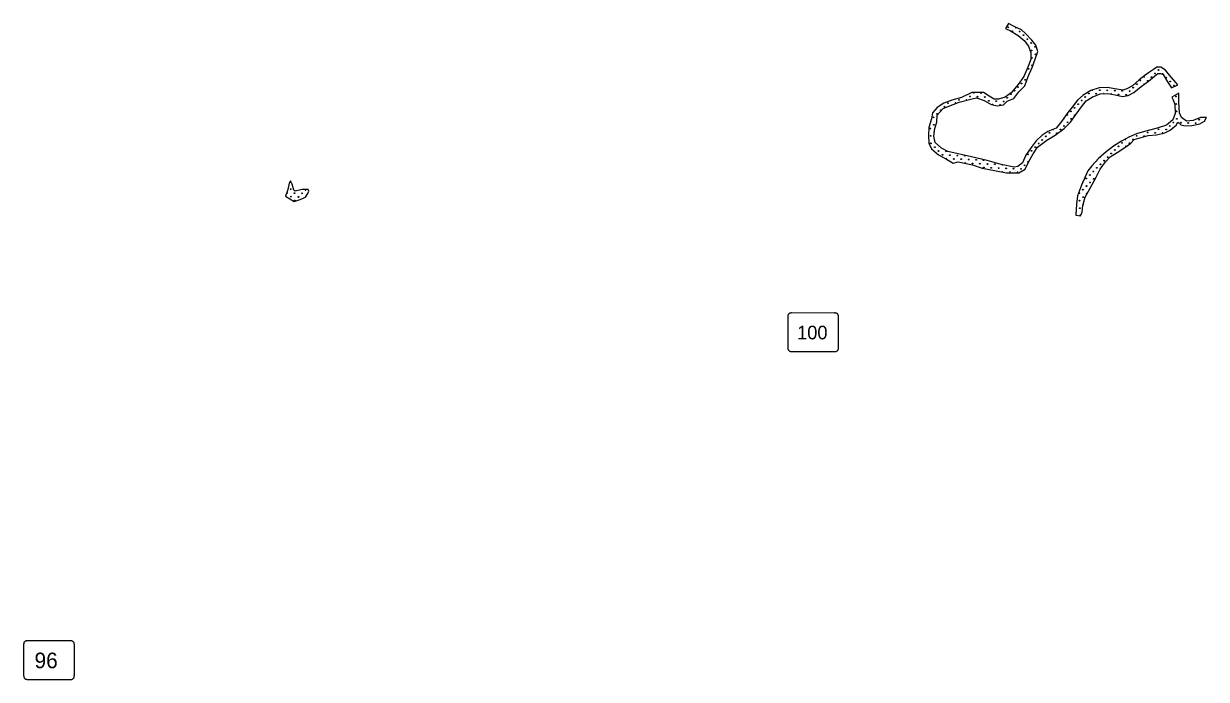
# Model space of a CAD drawing. Extents: x 1612280 to 1883141, y 560852 to 780851.
# Drawn here: x 1662813 to 1694849, y 612064 to 629833 of the extents above; entities that cross this region are included whole.
import ezdxf

# ---------------------------------------------------------------- set-up
doc = ezdxf.new("R2010")
doc.units = 0
for name, color, linetype in [('DESIGN - ROW - Slope Lines', 7, 'Continuous'), ('DESIGN - SCRATCH - User 1', 7, 'Continuous'), ('DESIGN - TRAFFIC CONTROL PERMANENT - Pavement Marking Text', 7, 'Continuous')]:
    doc.layers.add(name, color=color, linetype=linetype)

msp = doc.modelspace()

# ---------------------------------------------------------------- linework, layer by layer
at = {"layer": 'DESIGN - ROW - Slope Lines'}
for p, q in [((1683512, 621892), (1683512, 621060)), ((1683512, 621892), (1683512, 621060)), ((1662813, 613006), (1662813, 612174)), ((1662813, 613006), (1662813, 612174))]:
    msp.add_line(p, q, dxfattribs=at)
for points in [[(1684885, 621881), (1684885, 621889), (1684884, 621897), (1684883, 621912), (1684882, 621922), (1684880, 621933), (1684878, 621939), (1684875, 621945), (1684871, 621953), (1684865, 621960), (1684860, 621966), (1684855, 621971), (1684850, 621975), (1684843, 621980), (1684838, 621983), (1684830, 621987), (1684824, 621989), (1684817, 621990), (1684808, 621992), (1684799, 621992), (1684791, 621993), (1684778, 621993), (1684769, 621992), (1683612, 621993), (1683602, 621993), (1683592, 621992), (1683583, 621991), (1683574, 621990), (1683570, 621988), (1683562, 621985), (1683556, 621982), (1683551, 621979), (1683542, 621972), (1683536, 621966), (1683531, 621960), (1683527, 621955), (1683521, 621945), (1683518, 621938), (1683516, 621933), (1683515, 621929), (1683514, 621925), (1683513, 621918), (1683512, 621909), (1683512, 621901), (1683512, 621894), (1683512, 621876)], [(1684885, 621881), (1684885, 621889), (1684884, 621897), (1684883, 621912), (1684882, 621922), (1684880, 621933), (1684878, 621939), (1684875, 621945), (1684871, 621953), (1684865, 621960), (1684860, 621966), (1684855, 621971), (1684850, 621975), (1684843, 621980), (1684838, 621983), (1684830, 621987), (1684824, 621989), (1684817, 621990), (1684808, 621992), (1684799, 621992), (1684791, 621993), (1684778, 621993), (1684769, 621992), (1683612, 621993), (1683602, 621993), (1683592, 621992), (1683583, 621991), (1683574, 621990), (1683570, 621988), (1683562, 621985), (1683556, 621982), (1683551, 621979), (1683542, 621972), (1683536, 621966), (1683531, 621960), (1683527, 621955), (1683521, 621945), (1683518, 621938), (1683516, 621933), (1683515, 621929), (1683514, 621925), (1683513, 621918), (1683512, 621909), (1683512, 621901), (1683512, 621894), (1683512, 621876)], [(1684775, 620950), (1684795, 620951), (1684812, 620951), (1684823, 620953), (1684835, 620958), (1684846, 620965), (1684855, 620972), (1684863, 620980), (1684869, 620987), (1684875, 620997), (1684879, 621005), (1684882, 621012), (1684883, 621020), (1684884, 621028), (1684884, 621038), (1684885, 621061), (1684885, 621881)], [(1684775, 620950), (1684795, 620951), (1684812, 620951), (1684823, 620953), (1684835, 620958), (1684846, 620965), (1684855, 620972), (1684863, 620980), (1684869, 620987), (1684875, 620997), (1684879, 621005), (1684882, 621012), (1684883, 621020), (1684884, 621028), (1684884, 621038), (1684885, 621061), (1684885, 621881)], [(1683512, 621060), (1683512, 621051), (1683512, 621041), (1683513, 621031), (1683514, 621022), (1683516, 621013), (1683519, 621005), (1683522, 620998), (1683526, 620990), (1683532, 620983), (1683537, 620977), (1683545, 620970), (1683552, 620965), (1683560, 620960), (1683568, 620956), (1683577, 620953), (1683584, 620952), (1683599, 620951), (1683618, 620950), (1684775, 620950)], [(1683512, 621060), (1683512, 621051), (1683512, 621041), (1683513, 621031), (1683514, 621022), (1683516, 621013), (1683519, 621005), (1683522, 620998), (1683526, 620990), (1683532, 620983), (1683537, 620977), (1683545, 620970), (1683552, 620965), (1683560, 620960), (1683568, 620956), (1683577, 620953), (1683584, 620952), (1683599, 620951), (1683618, 620950), (1684775, 620950)], [(1664186, 612995), (1664186, 613003), (1664186, 613011), (1664185, 613026), (1664183, 613036), (1664181, 613047), (1664179, 613053), (1664176, 613059), (1664172, 613067), (1664166, 613074), (1664162, 613080), (1664156, 613085), (1664151, 613089), (1664145, 613094), (1664140, 613096), (1664131, 613100), (1664125, 613103), (1664118, 613104), (1664109, 613105), (1664101, 613106), (1664092, 613107), (1664080, 613107), (1664070, 613106), (1662913, 613107), (1662904, 613107), (1662893, 613106), (1662884, 613105), (1662875, 613103), (1662871, 613102), (1662864, 613099), (1662857, 613096), (1662852, 613092), (1662843, 613086), (1662837, 613080), (1662832, 613074), (1662828, 613069), (1662822, 613059), (1662819, 613052), (1662817, 613047), (1662816, 613043), (1662816, 613039), (1662815, 613032), (1662814, 613023), (1662813, 613015), (1662813, 613008), (1662813, 612990)], [(1664186, 612995), (1664186, 613003), (1664186, 613011), (1664185, 613026), (1664183, 613036), (1664181, 613047), (1664179, 613053), (1664176, 613059), (1664172, 613067), (1664166, 613074), (1664162, 613080), (1664156, 613085), (1664151, 613089), (1664145, 613094), (1664140, 613096), (1664131, 613100), (1664125, 613103), (1664118, 613104), (1664109, 613105), (1664101, 613106), (1664092, 613107), (1664080, 613107), (1664070, 613106), (1662913, 613107), (1662904, 613107), (1662893, 613106), (1662884, 613105), (1662875, 613103), (1662871, 613102), (1662864, 613099), (1662857, 613096), (1662852, 613092), (1662843, 613086), (1662837, 613080), (1662832, 613074), (1662828, 613069), (1662822, 613059), (1662819, 613052), (1662817, 613047), (1662816, 613043), (1662816, 613039), (1662815, 613032), (1662814, 613023), (1662813, 613015), (1662813, 613008), (1662813, 612990)], [(1664076, 612064), (1664097, 612065), (1664114, 612065), (1664124, 612067), (1664136, 612072), (1664147, 612079), (1664156, 612085), (1664164, 612093), (1664171, 612101), (1664177, 612111), (1664180, 612119), (1664183, 612126), (1664184, 612134), (1664185, 612142), (1664185, 612152), (1664186, 612175), (1664186, 612995)], [(1664076, 612064), (1664097, 612065), (1664114, 612065), (1664124, 612067), (1664136, 612072), (1664147, 612079), (1664156, 612085), (1664164, 612093), (1664171, 612101), (1664177, 612111), (1664180, 612119), (1664183, 612126), (1664184, 612134), (1664185, 612142), (1664185, 612152), (1664186, 612175), (1664186, 612995)], [(1662813, 612174), (1662813, 612165), (1662814, 612155), (1662814, 612145), (1662816, 612136), (1662817, 612127), (1662820, 612119), (1662823, 612112), (1662828, 612104), (1662833, 612097), (1662839, 612091), (1662846, 612084), (1662853, 612079), (1662861, 612074), (1662870, 612070), (1662878, 612067), (1662886, 612066), (1662901, 612065), (1662919, 612064), (1664076, 612064)], [(1662813, 612174), (1662813, 612165), (1662814, 612155), (1662814, 612145), (1662816, 612136), (1662817, 612127), (1662820, 612119), (1662823, 612112), (1662828, 612104), (1662833, 612097), (1662839, 612091), (1662846, 612084), (1662853, 612079), (1662861, 612074), (1662870, 612070), (1662878, 612067), (1662886, 612066), (1662901, 612065), (1662919, 612064), (1664076, 612064)]]:
    msp.add_lwpolyline(points, dxfattribs=at)
at = {"layer": 'DESIGN - SCRATCH - User 1'}
for points in [[(1689491, 629833), (1689407, 629705), (1689543, 629635), (1689754, 629510), (1689910, 629378), (1690035, 629226), (1690091, 629045), (1690091, 628865), (1690015, 628656), (1689904, 628403), (1689754, 628184), (1689560, 627955), (1689400, 627844), (1689220, 627785), (1689102, 627785), (1688970, 627872), (1688814, 627965), (1688495, 627969)], [(1689491, 629833), (1689407, 629705), (1689543, 629635), (1689754, 629510), (1689910, 629378), (1690035, 629226), (1690091, 629045), (1690091, 628865), (1690015, 628656), (1689904, 628403), (1689754, 628184), (1689560, 627955), (1689400, 627844), (1689220, 627785), (1689102, 627785), (1688970, 627872), (1688814, 627965), (1688495, 627969)], [(1688505, 627799), (1688620, 627820), (1688832, 627747), (1689022, 627646), (1689189, 627608), (1689355, 627629), (1689453, 627736), (1689636, 627809), (1689768, 627986), (1689931, 628146), (1690025, 628403), (1690133, 628646), (1690212, 628875), (1690282, 629076), (1690230, 629246), (1690126, 629385), (1689949, 629566), (1689845, 629666), (1689661, 629743), (1689491, 629833)], [(1688505, 627799), (1688620, 627820), (1688832, 627747), (1689022, 627646), (1689189, 627608), (1689355, 627629), (1689453, 627736), (1689636, 627809), (1689768, 627986), (1689931, 628146), (1690025, 628403), (1690133, 628646), (1690212, 628875), (1690282, 629076), (1690230, 629246), (1690126, 629385), (1689949, 629566), (1689845, 629666), (1689661, 629743), (1689491, 629833)], [(1694074, 628179), (1693853, 628436), (1693741, 628575), (1693620, 628650), (1693504, 628650), (1693415, 628594), (1693228, 628463), (1693030, 628308), (1692846, 628149), (1692697, 628067), (1692589, 628034), (1692421, 628057), (1692164, 628107), (1691950, 628097), (1691719, 628021), (1691515, 627896), (1691357, 627764), (1691212, 627573), (1691095, 627426)], [(1694074, 628179), (1693853, 628436), (1693741, 628575), (1693620, 628650), (1693504, 628650), (1693415, 628594), (1693228, 628463), (1693030, 628308), (1692846, 628149), (1692697, 628067), (1692589, 628034), (1692421, 628057), (1692164, 628107), (1691950, 628097), (1691719, 628021), (1691515, 627896), (1691357, 627764), (1691212, 627573), (1691095, 627426)], [(1691171, 627162), (1691324, 627381), (1691466, 627579), (1691594, 627737), (1691759, 627843), (1691976, 627929), (1692184, 627942), (1692381, 627906), (1692576, 627856), (1692727, 627886), (1692885, 627971), (1693079, 628130), (1693284, 628275), (1693448, 628410), (1693537, 628479), (1693606, 628479), (1693679, 628453), (1693797, 628258), (1693906, 628090), (1694074, 628179)], [(1691171, 627162), (1691324, 627381), (1691466, 627579), (1691594, 627737), (1691759, 627843), (1691976, 627929), (1692184, 627942), (1692381, 627906), (1692576, 627856), (1692727, 627886), (1692885, 627971), (1693079, 628130), (1693284, 628275), (1693448, 628410), (1693537, 628479), (1693606, 628479), (1693679, 628453), (1693797, 628258), (1693906, 628090), (1694074, 628179)], [(1688495, 627969), (1688221, 627833), (1687951, 627764), (1687740, 627681), (1687559, 627563), (1687434, 627418), (1687404, 627250), (1687332, 627022), (1687325, 626805), (1687335, 626597), (1687404, 626442), (1687592, 626274), (1687810, 626165), (1687987, 626053), (1688123, 626086), (1688514, 626004)], [(1688495, 627969), (1688221, 627833), (1687951, 627764), (1687740, 627681), (1687559, 627563), (1687434, 627418), (1687404, 627250), (1687332, 627022), (1687325, 626805), (1687335, 626597), (1687404, 626442), (1687592, 626274), (1687810, 626165), (1687987, 626053), (1688123, 626086), (1688514, 626004)], [(1694849, 627291), (1694694, 627289), (1694491, 627206), (1694311, 627186), (1694178, 627286), (1694123, 627416), (1694101, 627713), (1694101, 627951), (1693915, 627840)], [(1694849, 627291), (1694694, 627289), (1694491, 627206), (1694311, 627186), (1694178, 627286), (1694123, 627416), (1694101, 627713), (1694101, 627951), (1693915, 627840)], [(1688491, 626228), (1687846, 626366), (1687675, 626459), (1687500, 626614), (1687470, 626782), (1687490, 626996), (1687549, 627167), (1687553, 627352), (1687724, 627530), (1687826, 627583), (1688152, 627704), (1688505, 627799)], [(1688491, 626228), (1687846, 626366), (1687675, 626459), (1687500, 626614), (1687470, 626782), (1687490, 626996), (1687549, 627167), (1687553, 627352), (1687724, 627530), (1687826, 627583), (1688152, 627704), (1688505, 627799)], [(1693915, 627840), (1693948, 627765), (1693996, 627638), (1694001, 627402), (1693940, 627225), (1693766, 627078), (1693519, 626998), (1693170, 626906)], [(1693915, 627840), (1693948, 627765), (1693996, 627638), (1694001, 627402), (1693940, 627225), (1693766, 627078), (1693519, 626998), (1693170, 626906)], [(1691095, 627426), (1690924, 627179), (1690779, 626998), (1690555, 626909), (1690393, 626800), (1690239, 626658), (1690104, 626480), (1689962, 626269), (1689866, 626058), (1689741, 625959), (1689643, 625940), (1689287, 626019), (1688915, 626121), (1688491, 626228)], [(1691095, 627426), (1690924, 627179), (1690779, 626998), (1690555, 626909), (1690393, 626800), (1690239, 626658), (1690104, 626480), (1689962, 626269), (1689866, 626058), (1689741, 625959), (1689643, 625940), (1689287, 626019), (1688915, 626121), (1688491, 626228)], [(1694076, 627161), (1694159, 627092), (1694273, 627067), (1694455, 627072), (1694671, 627117), (1694796, 627194), (1694849, 627291)], [(1694076, 627161), (1694159, 627092), (1694273, 627067), (1694455, 627072), (1694671, 627117), (1694796, 627194), (1694849, 627291)], [(1688514, 626004), (1688780, 625917), (1689106, 625854), (1689432, 625788), (1689771, 625791), (1689942, 625893), (1690044, 626098), (1690156, 626305), (1690278, 626487), (1690529, 626675), (1690756, 626813), (1690993, 626988), (1691171, 627162)], [(1688514, 626004), (1688780, 625917), (1689106, 625854), (1689432, 625788), (1689771, 625791), (1689942, 625893), (1690044, 626098), (1690156, 626305), (1690278, 626487), (1690529, 626675), (1690756, 626813), (1690993, 626988), (1691171, 627162)], [(1691309, 624640), (1691437, 624625), (1691485, 624724), (1691503, 624903), (1691569, 625134), (1691701, 625376), (1691866, 625669), (1691972, 625892), (1692115, 626090), (1692239, 626226), (1692433, 626339), (1692671, 626497), (1692806, 626596), (1692898, 626691), (1693275, 626804), (1693498, 626823), (1693725, 626870), (1693872, 626944), (1694033, 627079), (1694076, 627161)], [(1691309, 624640), (1691437, 624625), (1691485, 624724), (1691503, 624903), (1691569, 625134), (1691701, 625376), (1691866, 625669), (1691972, 625892), (1692115, 626090), (1692239, 626226), (1692433, 626339), (1692671, 626497), (1692806, 626596), (1692898, 626691), (1693275, 626804), (1693498, 626823), (1693725, 626870), (1693872, 626944), (1694033, 627079), (1694076, 627161)], [(1693170, 626906), (1692953, 626848), (1692751, 626757), (1692550, 626647), (1692334, 626511), (1692136, 626361), (1691931, 626182), (1691745, 625984), (1691635, 625848), (1691463, 625456), (1691360, 625171), (1691335, 624940), (1691309, 624640)], [(1693170, 626906), (1692953, 626848), (1692751, 626757), (1692550, 626647), (1692334, 626511), (1692136, 626361), (1691931, 626182), (1691745, 625984), (1691635, 625848), (1691463, 625456), (1691360, 625171), (1691335, 624940), (1691309, 624640)], [(1670041, 625571), (1670009, 625506), (1669973, 625343), (1669908, 625160)], [(1670041, 625571), (1670009, 625506), (1669973, 625343), (1669908, 625160)], [(1670521, 625335), (1670361, 625340), (1670166, 625293), (1670133, 625320), (1670089, 625480), (1670041, 625571)], [(1670521, 625335), (1670361, 625340), (1670166, 625293), (1670133, 625320), (1670089, 625480), (1670041, 625571)], [(1669908, 625160), (1670139, 625012), (1670302, 625068), (1670444, 625130), (1670512, 625234), (1670535, 625296), (1670521, 625335)], [(1669908, 625160), (1670139, 625012), (1670302, 625068), (1670444, 625130), (1670512, 625234), (1670535, 625296), (1670521, 625335)]]:
    msp.add_lwpolyline(points, dxfattribs=at)
for centre in [(1690001, 629413), (1690001, 629413), (1690105, 629309), (1690105, 629309), (1693162, 626784), (1693162, 626784)]:
    msp.add_circle(centre, 10.6, dxfattribs=at)
at = {"layer": 'DESIGN - TRAFFIC CONTROL PERMANENT - Pavement Marking Text'}
for centre in [(1689485, 629734), (1689485, 629734), (1689590, 629630), (1689590, 629630), (1689792, 629622), (1689792, 629622), (1689896, 629518), (1689896, 629518), (1690210, 629204), (1690210, 629204), (1690113, 629107), (1690113, 629107), (1690120, 628906), (1690120, 628906), (1690217, 629003), (1690217, 629003), (1690031, 628607), (1690031, 628607), (1690128, 628704), (1690128, 628704), (1693555, 628577), (1693555, 628577), (1689844, 628211), (1689844, 628211), (1689941, 628308), (1689941, 628308), (1693062, 628293), (1693062, 628293), (1693159, 628390), (1693159, 628390), (1693264, 628286), (1693264, 628286), (1693361, 628383), (1693361, 628383), (1693458, 628480), (1693458, 628480), (1693660, 628473), (1693660, 628473), (1693764, 628368), (1693764, 628368), (1693869, 628263), (1693869, 628263), (1688545, 627957), (1688545, 627957), (1688746, 627950), (1688746, 627950), (1689553, 627920), (1689553, 627920), (1689650, 628017), (1689650, 628017), (1689747, 628114), (1689747, 628114), (1691666, 627942), (1691666, 627942), (1691867, 627935), (1691867, 627935), (1691965, 628032), (1691965, 628032), (1692166, 628025), (1692166, 628025), (1692368, 628017), (1692368, 628017), (1692472, 627913), (1692472, 627913), (1692569, 628010), (1692569, 628010), (1692674, 627905), (1692674, 627905), (1692771, 628002), (1692771, 628002), (1692868, 628099), (1692868, 628099), (1692965, 628196), (1692965, 628196), (1693973, 628159), (1693973, 628159), (1687753, 627584), (1687753, 627584), (1687850, 627681), (1687850, 627681), (1688149, 627771), (1688149, 627771), (1688448, 627860), (1688448, 627860), (1688649, 627853), (1688649, 627853), (1688851, 627845), (1688851, 627845), (1688955, 627741), (1688955, 627741), (1689157, 627733), (1689157, 627733), (1689261, 627629), (1689261, 627629), (1689359, 627726), (1689359, 627726), (1689456, 627823), (1689456, 627823), (1691375, 627651), (1691375, 627651), (1691472, 627748), (1691472, 627748), (1691569, 627845), (1691569, 627845), (1694028, 627859), (1694028, 627859), (1694035, 627657), (1694035, 627657), (1687462, 627293), (1687462, 627293), (1687559, 627390), (1687559, 627390), (1687656, 627487), (1687656, 627487), (1691083, 627360), (1691083, 627360), (1691180, 627457), (1691180, 627457), (1691188, 627255), (1691188, 627255), (1691278, 627554), (1691278, 627554), (1691285, 627352), (1691285, 627352), (1694043, 627456), (1694043, 627456), (1694050, 627254), (1694050, 627254), (1687372, 626994), (1687372, 626994), (1687469, 627091), (1687469, 627091), (1690897, 626964), (1690897, 626964), (1690994, 627061), (1690994, 627061), (1691091, 627158), (1691091, 627158), (1693557, 626970), (1693557, 626970), (1693759, 626963), (1693759, 626963), (1693856, 627060), (1693856, 627060), (1693953, 627157), (1693953, 627157), (1694155, 627150), (1694155, 627150), (1694356, 627142), (1694356, 627142), (1694558, 627135), (1694558, 627135), (1694655, 627232), (1694655, 627232), (1687380, 626792), (1687380, 626792), (1690404, 626680), (1690404, 626680), (1690501, 626778), (1690501, 626778), (1690598, 626875), (1690598, 626875), (1690800, 626867), (1690800, 626867), (1692863, 626694), (1692863, 626694), (1692960, 626791), (1692960, 626791), (1693259, 626881), (1693259, 626881), (1693460, 626873), (1693460, 626873), (1687387, 626591), (1687387, 626591), (1687492, 626486), (1687492, 626486), (1687596, 626382), (1687596, 626382), (1687798, 626374), (1687798, 626374), (1690016, 626292), (1690016, 626292), (1690113, 626389), (1690113, 626389), (1690210, 626486), (1690210, 626486), (1690307, 626583), (1690307, 626583), (1692273, 626313), (1692273, 626313), (1692370, 626410), (1692370, 626410), (1692467, 626507), (1692467, 626507), (1692564, 626604), (1692564, 626604), (1692766, 626597), (1692766, 626597), (1687701, 626277), (1687701, 626277), (1687902, 626270), (1687902, 626270), (1688007, 626165), (1688007, 626165), (1688104, 626262), (1688104, 626262), (1688209, 626158), (1688209, 626158), (1688306, 626255), (1688306, 626255), (1688410, 626150), (1688410, 626150), (1688515, 626046), (1688515, 626046), (1688612, 626143), (1688612, 626143), (1688716, 626038), (1688716, 626038), (1688813, 626135), (1688813, 626135), (1688918, 626031), (1688918, 626031), (1689120, 626023), (1689120, 626023), (1689926, 625993), (1689926, 625993), (1690023, 626091), (1690023, 626091), (1691982, 626022), (1691982, 626022), (1692079, 626119), (1692079, 626119), (1692176, 626216), (1692176, 626216), (1688821, 625934), (1688821, 625934), (1689023, 625926), (1689023, 625926), (1689224, 625919), (1689224, 625919), (1689426, 625911), (1689426, 625911), (1689530, 625807), (1689530, 625807), (1689627, 625904), (1689627, 625904), (1689829, 625896), (1689829, 625896), (1691690, 625731), (1691690, 625731), (1691788, 625828), (1691788, 625828), (1691885, 625925), (1691885, 625925), (1670047, 625346), (1670047, 625346), (1691504, 625335), (1691504, 625335), (1691593, 625634), (1691593, 625634), (1691601, 625432), (1691601, 625432), (1691698, 625529), (1691698, 625529), (1691795, 625626), (1691795, 625626), (1670054, 625145), (1670054, 625145), (1670151, 625242), (1670151, 625242), (1670159, 625040), (1670159, 625040), (1670256, 625137), (1670256, 625137), (1670353, 625234), (1670353, 625234), (1691407, 625238), (1691407, 625238), (1691414, 625036), (1691414, 625036), (1691511, 625133), (1691511, 625133), (1691608, 625231), (1691608, 625231), (1691422, 624835), (1691422, 624835)]:
    msp.add_circle(centre, 10.6, dxfattribs=at)
for centre, start, end in [((1689687, 629727), 132.0512, 2.8362), ((1693757, 628570), 184.2591, 253.683), ((1693256, 628487), 237.0292, 13.1235), ((1691763, 628039), 220.3081, 356.0919), ((1692069, 627927), 45.4663, 141.8046), ((1692271, 627920), 22.4092, 136.8007), ((1693167, 628189), 48.0428, 202.7168), ((1688052, 627674), 344.5591, 236.4513), ((1688350, 627763), 343.2242, 226.6698), ((1689060, 627636), 353.3986, 160.7729), ((1691770, 627838), 80.0474, 142.9793), ((1690986, 627263), 215.4915, 75.0753), ((1691382, 627450), 100.9882, 187.7934), ((1694147, 627351), 95.5543, 310.5222), ((1690695, 626972), 242.1168, 341.2202), ((1687477, 626890), 65.597, 283.8639), ((1687484, 626688), 86.0134, 293.9883), ((1690703, 626770), 89.8573, 152.8325), ((1692661, 626702), 178.6306, 58.6246), ((1693662, 626866), 317.6165, 246.0819), ((1692669, 626500), 14.4736, 235.1633), ((1687805, 626173), 305.7847, 179.6747), ((1688313, 626053), 307.4038, 208.8525), ((1689321, 626016), 193.9674, 320.9585), ((1689919, 626195), 304.2499, 7.0258), ((1691780, 626030), 258.7313, 14.5787), ((1691877, 626127), 235.6061, 37.7039), ((1691974, 626224), 239.8329, 22.5761), ((1689329, 625814), 318.2415, 198.9007), ((1689732, 625799), 307.6057, 233.5062), ((1691892, 625723), 67.7722, 241.403), ((1670039, 625548), 188.6739, 118.232), ((1670450, 625331), 144.275, 31.4752), ((1691496, 625537), 255.1952, 57.4049), ((1669950, 625249), 189.7121, 131.2389), ((1691325, 624738), 223.3043, 126.9433), ((1691519, 624932), 116.6391, 211.4897), ((1691429, 624633), 310.3807, 216.573)]:
    msp.add_arc(centre, 10.6, start, end, dxfattribs=at)

# ---------------------------------------------------------------- texts
at = {"layer": 'DESIGN - ROW - Slope Lines'}
for s, height, p in [('100', 369.6, (1683763, 621278)), ('100', 369.6, (1683763, 621278)), ('96', 422.4, (1663108, 612366)), ('96', 422.4, (1663108, 612366))]:
    msp.add_text(s, height=height, rotation=0.0011, dxfattribs=at).set_placement(p)

doc.saveas('drawing.dxf')
